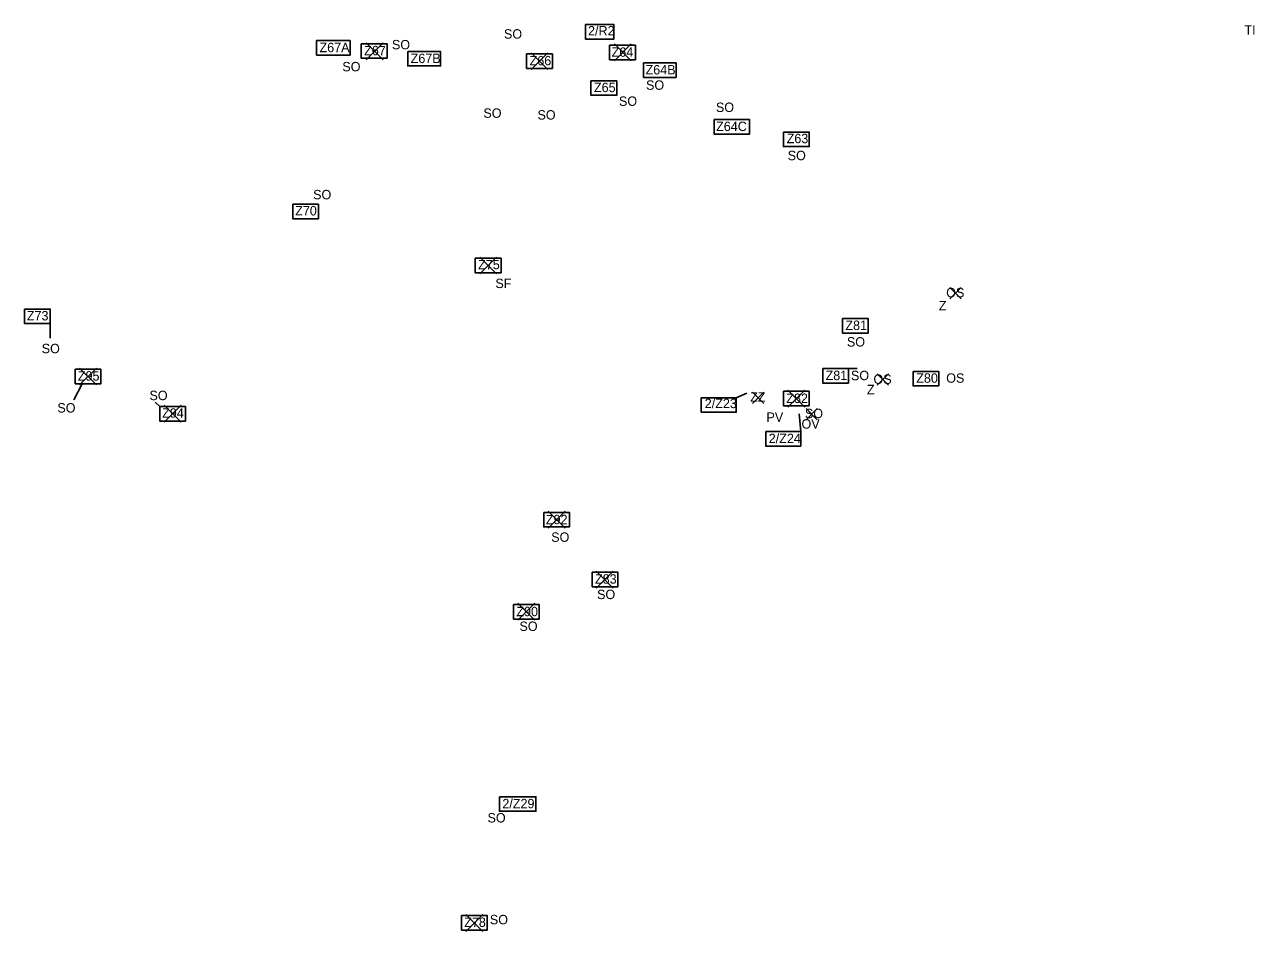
# Model space of a CAD drawing. Extents: x -443466 to -436070, y -1146578 to -1129775.
# Drawn here: x -442123 to -440814, y -1132601 to -1131637 of the extents above; entities that cross this region are included whole.
import ezdxf

# ---------------------------------------------------------------- set-up
doc = ezdxf.new("R2010")
doc.units = 0
for name, color, linetype in [('Vrstva 3', 7, 'Continuous'), ('Vrstva 4', 7, 'Continuous'), ('Vrstva 50', 7, 'Continuous'), ('Vrstva 85', 7, 'Continuous')]:
    doc.layers.add(name, color=color, linetype=linetype)

msp = doc.modelspace()

# ---------------------------------------------------------------- linework, layer by layer
at = {"layer": 'Vrstva 3'}
for p, q in [((-442095.6, -1131954.7), (-442095.6, -1131970.4)), ((-441246.1, -1132002.7), (-441236.7, -1132002.7)), ((-442061.8, -1132018.8), (-442070.5, -1132035.8)), ((-441365.6, -1132033.7), (-441354.3, -1132028.9)), ((-441979.2, -1132043), (-441984, -1132038.5)), ((-441979.2, -1132043), (-441984, -1132038.5)), ((-441296.9, -1132069.6), (-441298.7, -1132050.8))]:
    msp.add_line(p, q, dxfattribs=at)
for points in [[(-441526.1, -1131636.8), (-441495.7, -1131636.8), (-441495.7, -1131652.2), (-441526.1, -1131652.2)], [(-441812.2, -1131653.8), (-441776.5, -1131653.8), (-441776.5, -1131669.2), (-441812.2, -1131669.2)], [(-441764.6, -1131657.1), (-441737.2, -1131657.1), (-441737.2, -1131672.5), (-441764.6, -1131672.5)], [(-441715.1, -1131665.4), (-441680.3, -1131665.4), (-441680.3, -1131680.8), (-441715.1, -1131680.8)], [(-441588.7, -1131668), (-441561.3, -1131668), (-441561.3, -1131683.4), (-441588.7, -1131683.4)], [(-441500.3, -1131658.8), (-441472.9, -1131658.8), (-441472.9, -1131674.2), (-441500.3, -1131674.2)], [(-441464.2, -1131677.6), (-441429.6, -1131677.6), (-441429.6, -1131693), (-441464.2, -1131693)], [(-441520.2, -1131696.6), (-441492.8, -1131696.6), (-441492.8, -1131712), (-441520.2, -1131712)], [(-441389.1, -1131737.8), (-441351.3, -1131737.8), (-441351.3, -1131753.2), (-441389.1, -1131753.2)], [(-441315.3, -1131751.1), (-441287.9, -1131751.1), (-441287.9, -1131766.5), (-441315.3, -1131766.5)], [(-441837.6, -1131827.9), (-441810.3, -1131827.9), (-441810.3, -1131843.3), (-441837.6, -1131843.3)], [(-441643.3, -1131885.3), (-441615.9, -1131885.3), (-441615.9, -1131900.7), (-441643.3, -1131900.7)], [(-442123, -1131939.3), (-442095.6, -1131939.3), (-442095.6, -1131954.7), (-442123, -1131954.7)], [(-441252.4, -1131949.4), (-441225, -1131949.4), (-441225, -1131964.8), (-441252.4, -1131964.8)], [(-442069.1, -1132003.4), (-442041.7, -1132003.4), (-442041.7, -1132018.8), (-442069.1, -1132018.8)], [(-441273.5, -1132002.7), (-441246.1, -1132002.7), (-441246.1, -1132018.1), (-441273.5, -1132018.1)], [(-441177.4, -1132005.6), (-441150, -1132005.6), (-441150, -1132021), (-441177.4, -1132021)], [(-441402.8, -1132033.7), (-441365.6, -1132033.7), (-441365.6, -1132049.1), (-441402.8, -1132049.1)], [(-441315.4, -1132026.8), (-441288, -1132026.8), (-441288, -1132042.2), (-441315.4, -1132042.2)], [(-441979.2, -1132043), (-441951.8, -1132043), (-441951.8, -1132058.4), (-441979.2, -1132058.4)], [(-441334.2, -1132069.6), (-441296.9, -1132069.6), (-441296.9, -1132085), (-441334.2, -1132085)], [(-441570.4, -1132155.6), (-441543.1, -1132155.6), (-441543.1, -1132171), (-441570.4, -1132171)], [(-441518.9, -1132219.3), (-441491.5, -1132219.3), (-441491.5, -1132234.7), (-441518.9, -1132234.7)], [(-441602.6, -1132253.6), (-441575.2, -1132253.6), (-441575.2, -1132269), (-441602.6, -1132269)], [(-441617.7, -1132458.1), (-441578.7, -1132458.1), (-441578.7, -1132473.5), (-441617.7, -1132473.5)], [(-441657.9, -1132584.5), (-441630.5, -1132584.5), (-441630.5, -1132599.9), (-441657.9, -1132599.9)]]:
    msp.add_lwpolyline(points, close=True, dxfattribs=at)
at = {"layer": 'Vrstva 50'}
for p, q in [((-441138.1, -1131928.3), (-441126.1, -1131916.3)), ((-441138.1, -1131916.3), (-441126.1, -1131928.3)), ((-441138.1, -1131928.3), (-441126.1, -1131916.3)), ((-441138.1, -1131916.3), (-441126.1, -1131928.3)), ((-441138.1, -1131928.3), (-441126.1, -1131916.3)), ((-441138.1, -1131916.3), (-441126.1, -1131928.3)), ((-441138.1, -1131928.3), (-441126.1, -1131916.3)), ((-441138.1, -1131916.3), (-441126.1, -1131928.3)), ((-441215.6, -1132020.4), (-441203.6, -1132008.4)), ((-441215.6, -1132008.4), (-441203.6, -1132020.4)), ((-441215.6, -1132020.4), (-441203.6, -1132008.4)), ((-441215.6, -1132008.4), (-441203.6, -1132020.4)), ((-441215.6, -1132020.4), (-441203.6, -1132008.4)), ((-441215.6, -1132008.4), (-441203.6, -1132020.4)), ((-441215.6, -1132020.4), (-441203.6, -1132008.4)), ((-441215.6, -1132008.4), (-441203.6, -1132020.4)), ((-441348.1, -1132039.6), (-441336.1, -1132027.6)), ((-441348.1, -1132027.6), (-441336.1, -1132039.6)), ((-441348.1, -1132039.6), (-441336.1, -1132027.6)), ((-441348.1, -1132027.6), (-441336.1, -1132039.6)), ((-441291.3, -1132057), (-441279.3, -1132045)), ((-441291.3, -1132045), (-441279.3, -1132057))]:
    msp.add_line(p, q, dxfattribs=at)
at = {"layer": 'Vrstva 85'}
for p, q in [((-441759.5, -1131656.2), (-441741.5, -1131674.2)), ((-441741.5, -1131656.2), (-441759.5, -1131674.2)), ((-441584, -1131666.7), (-441566, -1131684.7)), ((-441566, -1131666.7), (-441584, -1131684.7)), ((-441495.3, -1131657.3), (-441477.3, -1131675.3)), ((-441477.3, -1131657.3), (-441495.3, -1131675.3)), ((-441638.6, -1131884), (-441620.6, -1131902)), ((-441620.6, -1131884), (-441638.6, -1131902)), ((-442064.4, -1132002.1), (-442046.4, -1132020.1)), ((-442046.4, -1132002.1), (-442064.4, -1132020.1)), ((-442064.4, -1132002.1), (-442046.4, -1132020.1)), ((-442046.4, -1132002.1), (-442064.4, -1132020.1)), ((-441310.7, -1132025.5), (-441292.7, -1132043.5)), ((-441292.7, -1132025.5), (-441310.7, -1132043.5)), ((-441974.5, -1132041.7), (-441956.5, -1132059.7)), ((-441956.5, -1132041.7), (-441974.5, -1132059.7)), ((-441565.8, -1132154.3), (-441547.8, -1132172.3)), ((-441547.8, -1132154.3), (-441565.8, -1132172.3)), ((-441514.5, -1132218.1), (-441496.5, -1132236.1)), ((-441496.5, -1132218.1), (-441514.5, -1132236.1)), ((-441597.9, -1132252.3), (-441579.9, -1132270.3)), ((-441579.9, -1132252.3), (-441597.9, -1132270.3)), ((-441653.2, -1132583.2), (-441635.2, -1132601.2)), ((-441635.2, -1132583.2), (-441653.2, -1132601.2))]:
    msp.add_line(p, q, dxfattribs=at)

# ---------------------------------------------------------------- texts
at = {"layer": 'Vrstva 3'}
for s, p in [('2/R2', (-441523.3, -1131648.3)), ('Z67A', (-441809.1, -1131666.1)), ('Z67', (-441761.6, -1131669.4)), ('Z67B', (-441712.1, -1131677.7)), ('Z66', (-441585.5, -1131680.1)), ('Z64', (-441498.2, -1131671)), ('Z64B', (-441462.1, -1131689.8)), ('Z64', (-441462.1, -1131689.8)), ('Z65', (-441517, -1131708.6)), ('Z64C', (-441387, -1131750)), ('Z64', (-441387, -1131750)), ('Z63', (-441311.9, -1131762.9)), ('Z70', (-441835, -1131839.8)), ('Z75', (-441640.3, -1131897)), ('Z73', (-442120.6, -1131951.4)), ('Z81', (-441249.4, -1131961.6)), ('Z95', (-442066.3, -1132015.4)), ('Z81', (-441270.5, -1132014.9)), ('Z80', (-441174, -1132017.7)), ('2/Z23', (-441399.1, -1132044.7)), ('Z82', (-441312.3, -1132039.2)), ('Z94', (-441976.6, -1132054.9)), ('2/Z24', (-441331, -1132081.9)), ('Z92', (-441568.2, -1132168.2)), ('Z83', (-441515.9, -1132231.4)), ('Z90', (-441599.6, -1132266)), ('2/Z29', (-441614.5, -1132470.3)), ('Z78', (-441655.1, -1132596.5))]:
    msp.add_text(s, height=10, dxfattribs=at).set_placement(p)
at = {"layer": 'Vrstva 4'}
for s, p in [('SO', (-441612.8, -1131651.7)), ('TI', (-440824.7, -1131647.6)), ('SO', (-441732, -1131663.1)), ('SO', (-441784.8, -1131686.5)), ('SO', (-441461.6, -1131706.1)), ('SO', (-441490.4, -1131723.2)), ('SO', (-441387.2, -1131729.7)), ('SO', (-441387.2, -1131729.7)), ('SO', (-441634.7, -1131735.9)), ('SO', (-441577.1, -1131737.8)), ('SO', (-441310.8, -1131781)), ('SO', (-441815.9, -1131822.6)), ('SF', (-441621.9, -1131917)), ('OS', (-441142.1, -1131926.8)), ('Z', (-441149.9, -1131940.6)), ('Z', (-441149.9, -1131940.6)), ('SO', (-441247.8, -1131979.2)), ('SO', (-442104.8, -1131986.3)), ('SO', (-441243.5, -1132015)), ('OS', (-441219.5, -1132018.9)), ('OS', (-441142.1, -1132017.7)), ('Z', (-441226.5, -1132029.9)), ('SO', (-441990.1, -1132036.2)), ('ZZ', (-441350.8, -1132037.9)), ('SO', (-442088.1, -1132049.4)), ('PV', (-441333.4, -1132059.3)), ('SO', (-441292.5, -1132055.4)), ('OV', (-441296.1, -1132066.5)), ('SO', (-441562.5, -1132186.9)), ('SO', (-441513.7, -1132247.8)), ('SO', (-441596.3, -1132281.7)), ('SO', (-441630.3, -1132485.4)), ('SO', (-441627.8, -1132593.7))]:
    msp.add_text(s, height=10, dxfattribs=at).set_placement(p)

doc.saveas('drawing.dxf')
